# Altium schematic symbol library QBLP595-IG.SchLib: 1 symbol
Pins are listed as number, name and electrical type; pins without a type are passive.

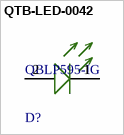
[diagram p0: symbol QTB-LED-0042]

## QTB-LED-0042
designator D?, comment QBLP595-IG
LED GREEN CLEAR 0402 SMD; Manufacturer: QT Brightek (QTB); Luminous Intensity: 600mcd; Viewing Angle: 140°; Forward Voltage: 3.1V; Test Current: 20mA; Dominant Wavelength: 520nm; Lens Style: Flat; Lens Color: Colorless; Lens Size: 0.5mm
footprint FP-QBLP595-IG-MFG
pins: 1 CATHODE (-), 2 ANODE (+)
